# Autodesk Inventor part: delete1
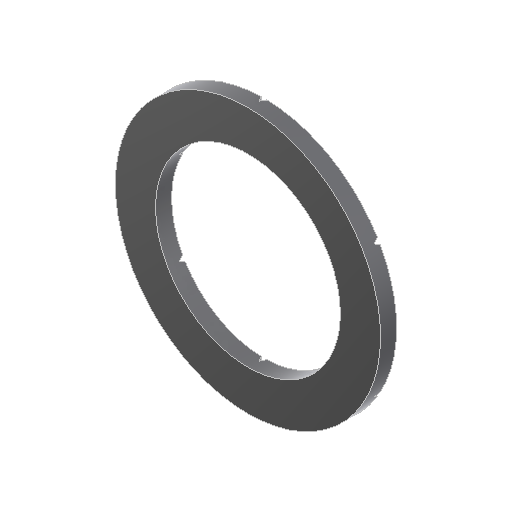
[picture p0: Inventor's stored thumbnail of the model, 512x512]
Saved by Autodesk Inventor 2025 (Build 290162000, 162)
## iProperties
Created: 2025-01
Part Number: delete1
Material: Thermoplastic Resin
Document SubType Name: Modeling
Designer: dansp
Density: 1.28 g/cm^3
Appearance: Smooth - Black
Mass: 15.0278 g
Surface Area: 81.5062 cm^2
Volume: 11.7404 cm^3
Author: dansp
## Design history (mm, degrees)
sketch "Sketch1"
  geometry: L1 (0, 57.75)-(0, -57.75) reference; L2 (-57.75, 0)-(57.75, 0) reference; C1 r 41.25 at (0, 0); C2 r 28.75 at (0, 0); 1 further point
  constraints: 2 centre point, 2 coincident
  dimensions: "d0" = 82.5 diameter of C1; "d1" = 12.5 radial gap between concentric circles of C1 C2
extrude "Extrusion1" new body sketch "Sketch1" distance "d2" = 5; taper "d3" = 0 deg
sketch "Sketch5"
  geometry: L1 (-40.25, 0)-(40.25, 0) reference; L2 (0, -0.3)-(0, 1.8) reference; L3 (0.866, 0)-(0, 1.5); L4 (0, 1.5)-(-0.866, 0); L5 (-28.75, 0)-(28.75, 0) reference; 2 further points
  constraints: 4 end point, 3 point on line, 1 other
  dimensions: "d29" = 60 deg angle of L4 L3; "d30" = 1.5 distance from line of L3.end L1
extrude "Extrusion5" cut sketch "Sketch5" extent not by distance; stored distance "d31" = 0; taper "d32" = 0 deg
pattern_circular "Circular Pattern5" dims angle "d34" = 360 deg
body "Solid1"
